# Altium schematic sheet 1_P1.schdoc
size 307 x 218 mm; Symbol: Drawing-Symbol_A4; Device: Drawing-Symbol_A4; Company: 嘉立创EDA; Version: V1.0; Page Size: A4; @Project Name: zero_case; @Page Count: 1; @Update Date: 2026-06-30; @Create Date: 2026-06-26; @Schematic Name: Schematic1; @Page No: 1; @Page Name: P1; @Board Name: zero_case; @Create Time: 10:47:22; @Update Time: 11:21:50; Title Block Position: 3; Size: A4; Width: 1170; Height: 825; Region Start: 1; X Region Count: 6; Y Region Count: 4; Blade Width: 10
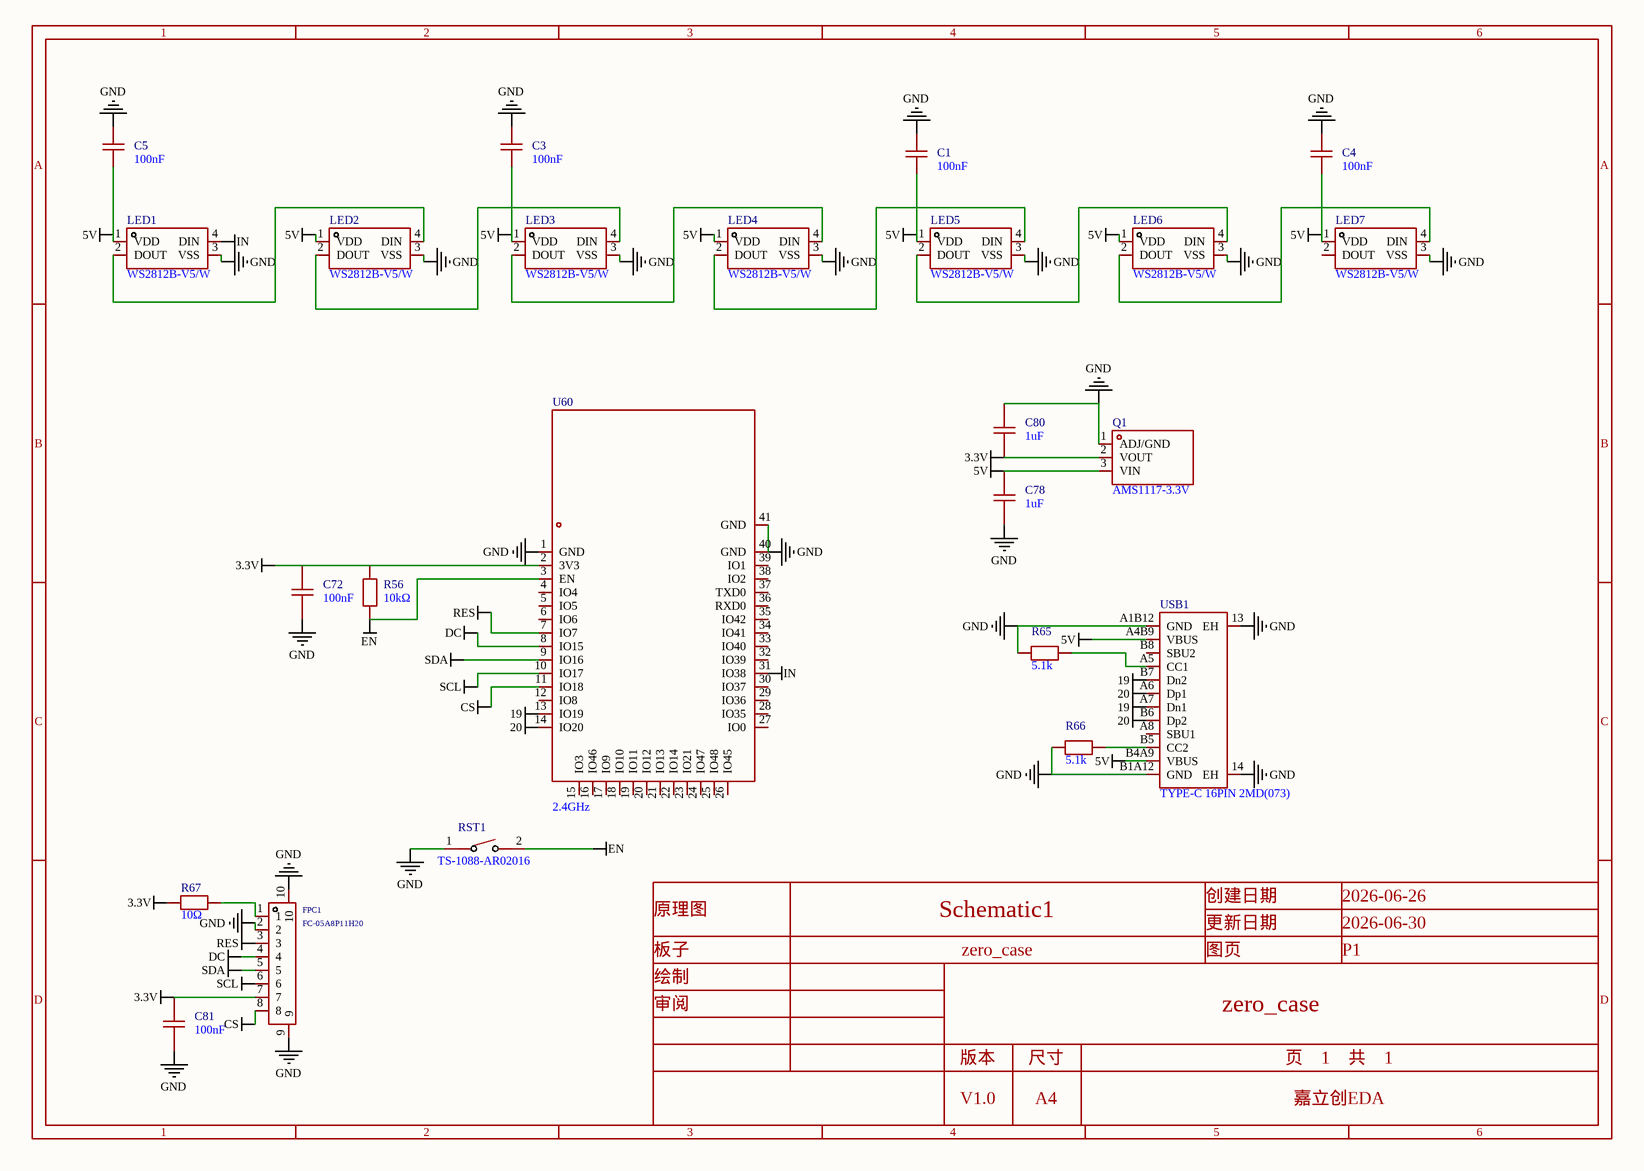
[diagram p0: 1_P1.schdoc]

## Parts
C1  100nF  [C0603]
C3  100nF  [C0603]
C4  100nF  [C0603]
C5  100nF  [C0603]
C72  100nF  [C0603]
C78  1uF  [C0805]
C80  1uF  [C0805]
C81  100nF  [C0603]
FPC1  FC-05A8P11H20  [FPC-SMD_8P-P0.50_FC05-S08FCT-00]
LED1  WS2812B-V5/W  [LED-SMD_4P-L5.0-W5.0-TL-1]
LED2  WS2812B-V5/W  [LED-SMD_4P-L5.0-W5.0-TL-1]
LED3  WS2812B-V5/W  [LED-SMD_4P-L5.0-W5.0-TL-1]
LED4  WS2812B-V5/W  [LED-SMD_4P-L5.0-W5.0-TL-1]
LED5  WS2812B-V5/W  [LED-SMD_4P-L5.0-W5.0-TL-1]
LED6  WS2812B-V5/W  [LED-SMD_4P-L5.0-W5.0-TL-1]
LED7  WS2812B-V5/W  [LED-SMD_4P-L5.0-W5.0-TL-1]
Q1  AMS1117-3.3V  [SOT-89-3_L4.5-W2.5-P1.50-LS4.2-BR]
R56  10kΩ  [R0603]
R65  5.1k  [R0603]
R66  5.1k  [R0603]
R67  10Ω  [R0603]
RST1  TS-1088-AR02016  [SW-SMD_L3.9-W3.0-P4.45]
U60  2.4GHz  [WIRELM-SMD_ESP32-S3-WROOM-1]
USB1  TYPE-C 16PIN 2MD(073)  [USB-C-SMD_TYPE-C-16PIN-2MD-073]

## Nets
3.3V: C72.1 C80.1 C81.1 FPC1.7 Q1.2(VOUT) R56.2 R67.2 U60.2(3V3)
5V: C1.1 C3.1 C4.1 C5.1 C78.2 LED1.1(VDD) LED2.1(VDD) LED3.1(VDD) LED4.1(VDD) LED5.1(VDD) LED6.1(VDD) LED7.1(VDD) Q1.3(VIN) USB1.A4B9(VBUS) USB1.B4A9(VBUS)
19: U60.13(IO19) USB1.A7(Dn1) USB1.B7(Dn2)
20: U60.14(IO20) USB1.A6(Dp1) USB1.B6(Dp2)
CS: FPC1.8 U60.11(IO18)
DC: FPC1.4 U60.8(IO15)
EN: R56.1 RST1.2 U60.3(EN)
GND: C1.2 C3.2 C4.2 C5.2 C72.2 C78.1 C80.2 C81.2 FPC1.2 FPC1.9 FPC1.10 LED1.3(VSS) LED2.3(VSS) LED3.3(VSS) LED4.3(VSS) LED5.3(VSS) LED6.3(VSS) LED7.3(VSS) Q1.1(ADJ/GND) R65.1 R66.1 RST1.1 U60.1(GND) U60.40(GND) U60.41(GND) USB1.13(EH) USB1.14(EH) USB1.A1B12(GND) USB1.B1A12(GND)
IN: LED1.4(DIN) U60.31(IO38)
RES: FPC1.3 U60.7(IO7)
SCL: FPC1.6 U60.10(IO17)
SDA: FPC1.5 U60.9(IO16)
NetFPC1_1: FPC1.1 R67.1
NetLED1_2: LED1.2(DOUT) LED2.4(DIN)
NetLED2_2: LED2.2(DOUT) LED3.4(DIN)
NetLED3_2: LED3.2(DOUT) LED4.4(DIN)
NetLED4_2: LED4.2(DOUT) LED5.4(DIN)
NetLED5_2: LED5.2(DOUT) LED6.4(DIN)
NetLED6_2: LED6.2(DOUT) LED7.4(DIN)
NetR65_2: R65.2 USB1.A5(CC1)
NetR66_2: R66.2 USB1.B5(CC2)

Not connected (* = marked no-connect by the designer): LED7 2(DOUT); U60 4(IO4) 5(IO5) 6(IO6) 12(IO8) 15(IO3) 16(IO46) 17(IO9) 18(IO10) 19(IO11) 20(IO12) 21(IO13) 22(IO14) 23(IO21) 24(IO47) 25(IO48) 26(IO45) 27(IO0) 28(IO35) 29(IO36) 30(IO37) 32(IO39) 33(IO40) 34(IO41) 35(IO42) 36(RXD0) 37(TXD0) 38(IO2) 39(IO1); USB1 A8(SBU1) B8(SBU2)

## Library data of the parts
C1 C3-C5 = 0603B104K500NT: Manufacturer: FH(风华); Add into BOM: yes; Tolerance: ±10%; Voltage Rating: 50V; Temperature Coefficient: X7R
C72 C81 = CGA0603X7R104K500JT: Manufacturer: HRE(芯声); Add into BOM: yes; Tolerance: ±10%; Voltage Rating: 50V; Temperature Coefficient: X7R
C78 C80 = 0805B105K500NT: Manufacturer: FH(风华); Symbol: 0805B105K500NT_C215803; Add into BOM: yes; Tolerance: ±10%; Voltage Rating: 50V; Temperature Coefficient: X7R
FPC1 = FC-05A8P11H20: Manufacturer: BXCONN(宝讯); Add into BOM: yes; Locking Feature: 翻盖式; Number of Contacts: 8P; Pitch: 0.5mm; FFC, FCB Thickness: 0.3mm
LED1-LED7 = WS2812B-V5/W: Manufacturer: worldsemi; Add into BOM: yes
Q1 = AMS1117-3.3V_C5120796: Manufacturer: MSKSEMI(美森科); Add into BOM: yes; Output Type: 固定; Voltage - Supply: 18V; Output Voltage: 3.3V; Output Current: 1A; Voltage Dropout: 1.4V@(1A); standby current: 12mA; Output Configuration: 正极; Number of Outputs: 1
R56 R65-R67 = FRC0603J472 TS: Manufacturer: FOJAN(富捷); Add into BOM: yes; Tolerance: ±5%; Power(Watts): 100mW; Voltage-Supply(Max): 75V; Temperature Coefficient: ±100ppm/℃
RST1 = TS-1088-AR02016: Manufacturer: XUNPU(讯普); Add into BOM: yes; Circuit: 单刀单掷; Actuator Style: 圆形按钮; Operating Force: 1.6N; Switch Height: 2mm; with Bracket: 不带支架; Contact Current: 50mA; Voltage Rating: 12V; Actuator/Cap Color: 黑色; Life: 10万次
U60 = ESP32-S3-WROOM-1-N8R2: Manufacturer: ESPRESSIF(乐鑫); Utilized IC / Part: ESP32-S3芯片; Symbol: ESP32-S3-WROOM-1(N8R2); Add into BOM: yes; Wireless Standard: Bluetooth5.0; Interface Type: SPI；I2S；USB；I2C；UART; Antenna Type: 板载PCB天线; Output Power: 20.5dBm; Voltage - Supply: 3V~3.6V; Receive  Current: 97mA; Send  Current: 355mA; Sensitivity: -98.2dBm
USB1 = TYPE-C 16PIN 2MD(073): Manufacturer: SHOU HAN(首韩); Add into BOM: yes; Gender: 母; Number of Contacts: 16P; Number of Ports: 1; Current Rating-Power: 3A; Voltage Rating: 5V; Connect-Disconnect Life: 1万次; Detection color: 黑色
